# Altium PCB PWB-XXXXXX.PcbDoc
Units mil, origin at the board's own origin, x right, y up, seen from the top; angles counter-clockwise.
Board outline 8000 x 6000 mil, 2 copper layers (L1 - Top Layer, L2 - Bottom Layer), stack 59.8 mil thick; 10 components, 0 nets, 12 pads, 0 vias.
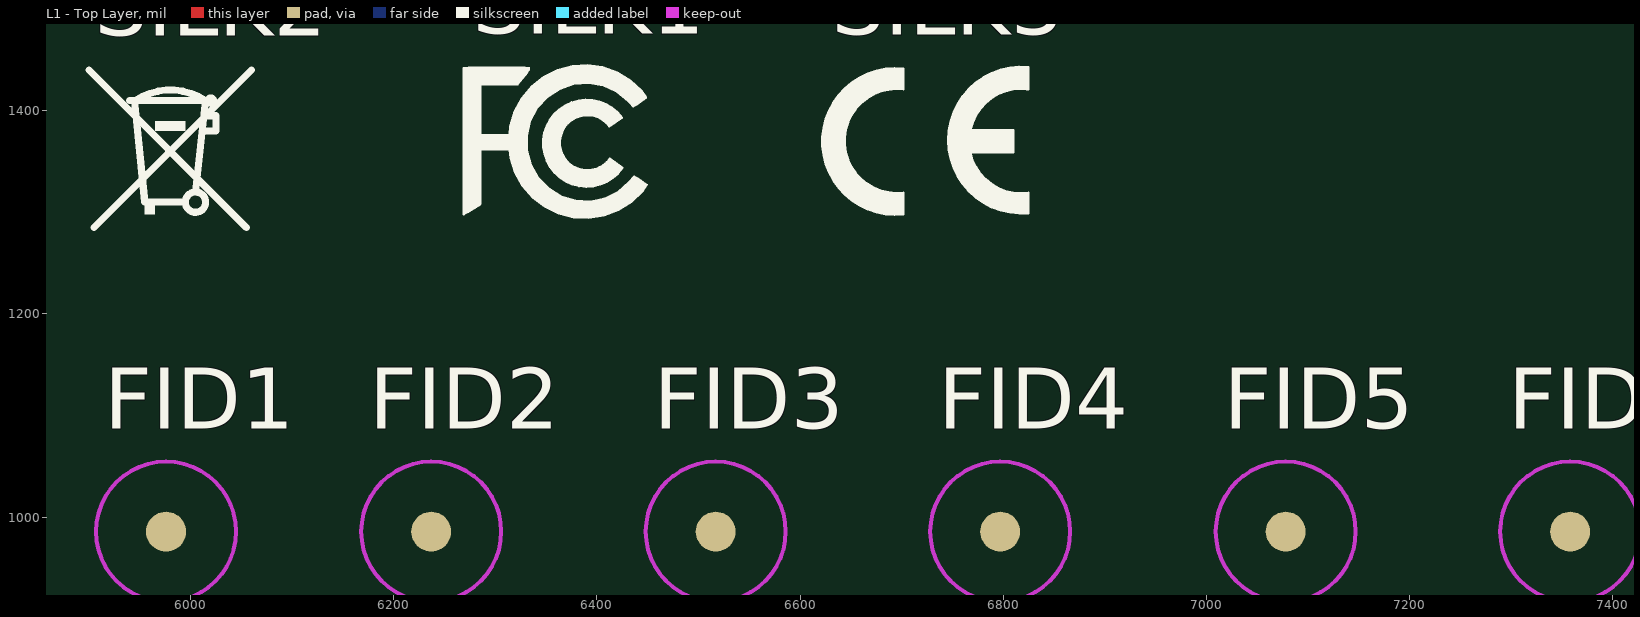
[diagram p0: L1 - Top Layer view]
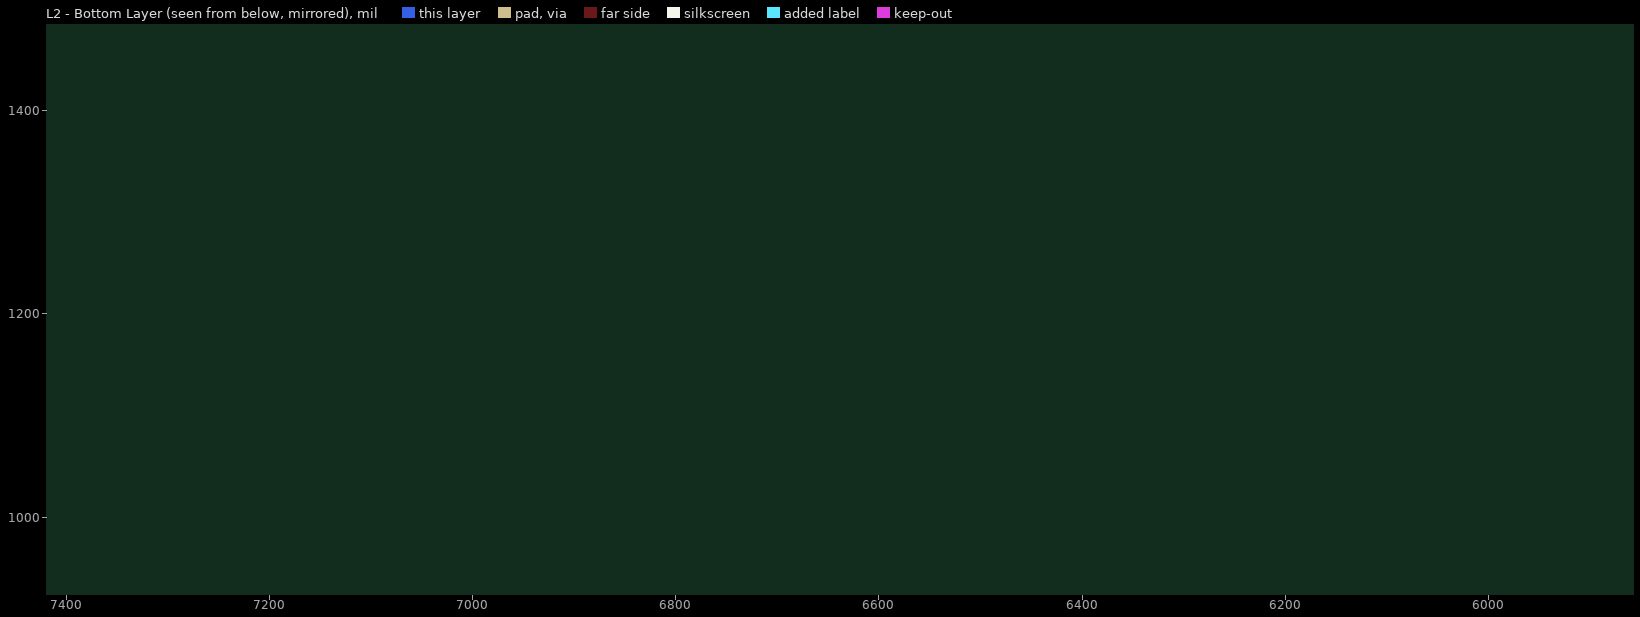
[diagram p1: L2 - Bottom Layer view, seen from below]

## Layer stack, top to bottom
Top Solder: solder mask 1, Solder Resist, Dk 4
L1 - Top Layer: signal copper 1.4
Dielectric 1: core 57, FR-4, Dk 4
L2 - Bottom Layer: signal copper 1.4
Bottom Solder: solder mask 1, Solder Resist, Dk 4

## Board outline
0,0 0,6000 8000,6000 8000,0

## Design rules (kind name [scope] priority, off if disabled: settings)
Clearance Clearance_pours [InPolygon] p1: gap=15 ignorepadtopadclearanceinfootprint=TRUE
Clearance [All] p2: gap=6 ignorepadtopadclearanceinfootprint=TRUE
ComponentClearance [All] p1: gap=10 collisioncheckmode=3 verticalgap=10 showdistances=FALSE donotcheckwithout3dbody=TRUE
HoleSize [All] p1: absolutevalues=TRUE maxlimit=1000 minlimit=6 maxpercent=80.000 minpercent=20.000
MinimumSolderMaskSliver [All] p1: minsoldermaskwidth=4
PlaneClearance PlaneClearance_big-hole [IsPad And HoleDiameter>100] p1: clearance=80
PlaneClearance [All] p2: clearance=24
PlaneConnect PlaneConnect_mounting-hole [HoleDiameter>100] p1: planeconnectstyle=Direct reliefexpansion=20 reliefentries=4 reliefconductorwidth=10 reliefairgap=10
PlaneConnect PlaneConnect_via [IsVia] p2: planeconnectstyle=Direct reliefexpansion=20 reliefentries=4 reliefconductorwidth=10 reliefairgap=10
PlaneConnect [All] p3: planeconnectstyle=Relief reliefexpansion=12 reliefentries=4 reliefconductorwidth=8 reliefairgap=10
PolygonConnect PolygonConnect_via [IsVia] p1: connectstyle=Direct reliefconductorwidth=10 reliefentries=4 polygonreliefangle="90 Angle" airgapwidth=10
PolygonConnect [All] p2: connectstyle=Relief reliefconductorwidth=10 reliefentries=4 polygonreliefangle="45 Angle" airgapwidth=10
RoutingVias [All] p1: holewidth=12 width=24 viastyle="Through Hole" minholewidth=8 minwidth=18 maxholewidth=10 maxwidth=20
SilkToSilkClearance [All] p1: silktosilkclearance=1
SilkToSolderMaskClearance [IsPad] p1: minsilkscreentomaskgap=1 clearancetoexposedcopper=TRUE
SolderMaskExpansion SolderMaskExpansion_via [IsVia] p1: expansion=4 istentingtop=TRUE
SolderMaskExpansion [All] p2: expansion=4 istentingtop=FALSE
Width [All] p1: maxlimit=1000 minlimit=6 preferedwidth=10 minimp=50.000000 maximp=50.000000 favimp=50.000000
23 further rules are at their usual default settings.

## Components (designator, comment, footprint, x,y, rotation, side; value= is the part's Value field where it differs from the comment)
FID1 "Fiducial, 1:3mm" "FIDUCIAL 1MM" 5976,985.71 r0 top
FID2 "Fiducial, 1:3mm" "FIDUCIAL 1MM" 6237,985.71 r0 top
FID3 "Fiducial, 1:3mm" "FIDUCIAL 1MM" 6517,985.71 r0 top
FID4 "Fiducial, 1:3mm" "FIDUCIAL 1MM" 6797,985.71 r0 top
FID5 "Fiducial, 1:3mm" "FIDUCIAL 1MM" 7078,985.71 r0 top
FID6 "Fiducial, 1:3mm" "FIDUCIAL 1MM" 7358,985.71 r0 top
"PCB PN (In Copper)1" "PCB PN (In Copper)" "PCB PN (In Copper)" 5910,640 r0 top
SILK1 "FCC - Silk Screen" "LOGO - FCC" 6390,1370 r0 top
SILK2 "Trash Can-Silk Screen" "LOGO - NO THROW" 5980,1360 r0 top
SILK3 "Conformité Européenne" "Logo - European Conformity" 6720,1370 r0 top

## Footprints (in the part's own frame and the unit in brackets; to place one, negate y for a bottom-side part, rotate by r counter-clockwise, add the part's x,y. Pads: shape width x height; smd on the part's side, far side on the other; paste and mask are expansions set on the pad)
"FIDUCIAL 1MM" [mm]
  round 0.4 smd paste-127 mask+1.3: 1(0,0)
  round 1 smd paste-1 mask+0: 1(0,0)
  L1 - Top Layer keep-out circle w0.1: c0,0 r1.75
"Logo - European Conformity" [mil]
  silkscreen extent -98,-73 105,74
"LOGO - FCC" [mil]
  silkscreen extent -122,-76 60,76
"LOGO - NO THROW" [mil]
  silkscreen extent -80,-75 80,80
"PCB PN (In Copper)" [mil] "PCB PN (In Copper)"

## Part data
FID1 FID2 FID3 FID4 FID5 FID6: library part "PCB - Fiducial"
"PCB PN (In Copper)1": library part "PCB - PN in CU", "PCB Part Number (In Copper)"
SILK1: library part "Silk Screen - FCC"
SILK2: library part "Silk Screen - No Throw Out"
SILK3: library part "Silkscreen - European Conformity"

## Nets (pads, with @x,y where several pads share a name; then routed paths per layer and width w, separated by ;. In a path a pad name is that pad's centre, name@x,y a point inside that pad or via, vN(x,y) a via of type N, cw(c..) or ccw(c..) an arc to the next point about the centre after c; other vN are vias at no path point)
pads on no net: FID1.1 FID2.1 FID3.1 FID4.1 FID5.1 FID6.1

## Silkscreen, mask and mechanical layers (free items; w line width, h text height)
M04_PCB_BoardOutline:
  the board outline again, w10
